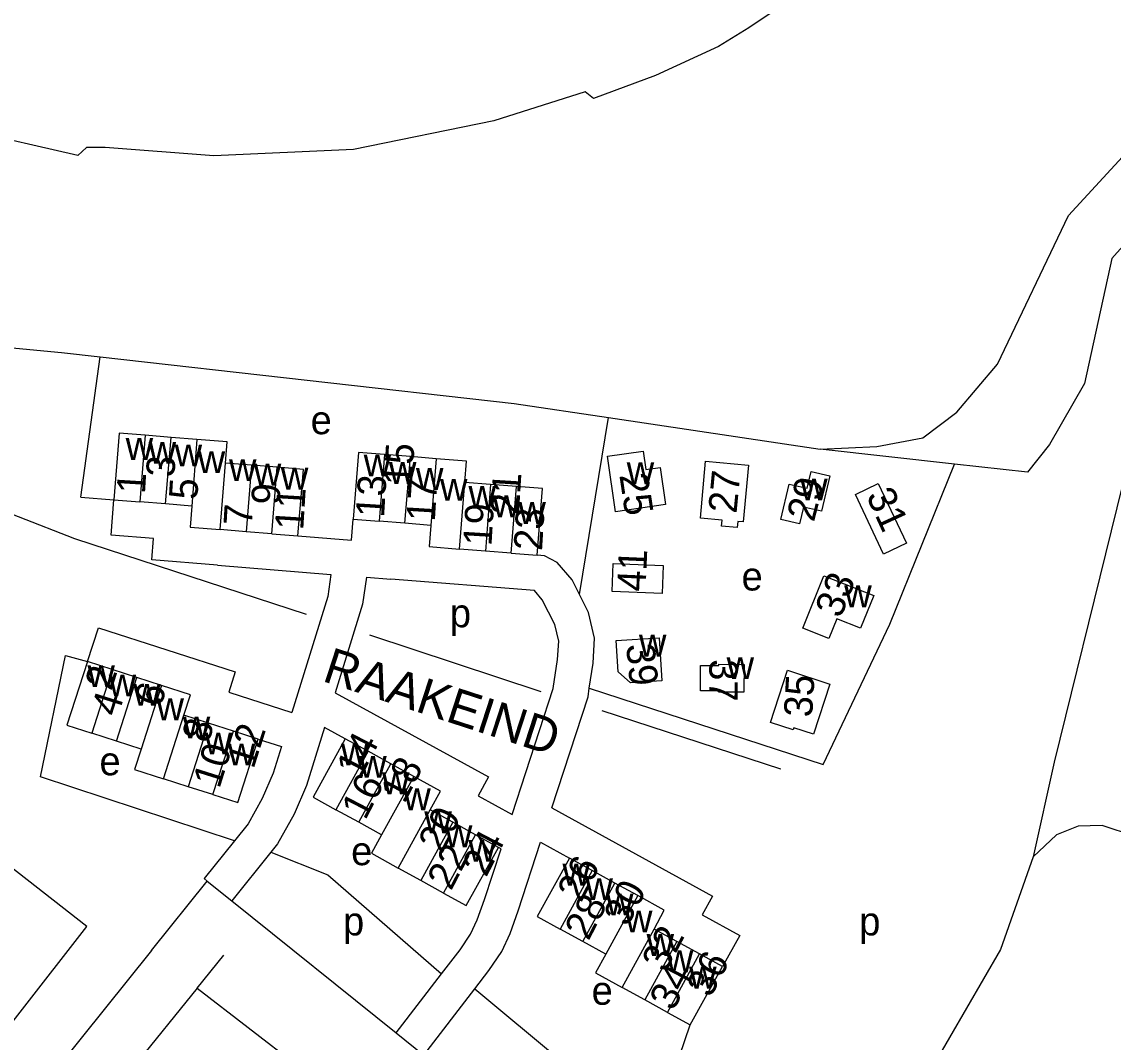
# Model space of a CAD drawing. Extents: x 159441 to 162086, y 388175 to 389787.
# Drawn here: x 160261 to 160414.4, y 389425.1 to 389568.6 of the extents above; entities that cross this region are included whole.
import ezdxf

# ---------------------------------------------------------------- set-up
doc = ezdxf.new("R2010")
doc.units = 0
for name, color, linetype in [('BLT_Basislijn', 7, 'Continuous'), ('BLT_Bebouwing', 7, 'Continuous'), ('BLT_Centroide', 7, 'Continuous'), ('BLT_Huisnummer', 7, 'Continuous'), ('BLT_Huisnummer_ tussenligend', 7, 'Continuous'), ('BLT_Huisnummer_zonder_bebouwing', 7, 'Continuous'), ('BLT_Onderverdeling_panden', 7, 'Continuous'), ('BLT_Plantopo', 7, 'Continuous'), ('BLT_Straatnaam', 7, 'Continuous')]:
    doc.layers.add(name, color=color, linetype=linetype)

msp = doc.modelspace()

# ---------------------------------------------------------------- linework, layer by layer
at = {"layer": 'BLT_Basislijn'}
for p, q in [((160269.3, 389501.74), (160272.05, 389521.43)), ((160339.43, 389488.02), (160343.47, 389512.9)), ((160343.47, 389512.9), (160373.24, 389508.47)), ((160392.13, 389506.37), (160373.24, 389508.47)), ((160269.3, 389501.74), (160273.96, 389501.36)), ((160307.34, 389495.68), (160307.58, 389498.63)), ((160299.83, 389496.3), (160307.34, 389495.68)), ((160288.51, 389492.17), (160304.46, 389490.87)), ((160309.45, 389490.46), (160312.87, 389490.18)), ((160333.1, 389488.59), (160312.87, 389490.18)), ((160334.03, 389474.34), (160309.95, 389482.3)), ((160290.1, 389474.31), (160298.98, 389471.44)), ((160406.13, 389464.49), (160403.2, 389451.16)), ((160325.19, 389459.75), (160329.97, 389457.12)), ((160296.04, 389451.83), (160290.53, 389444.96)), ((160296.49, 389452.39), (160296.44, 389452.33)), ((160403.2, 389451.16), (160398.61, 389438.15)), ((160279.23, 389437.97), (160287.07, 389447.73)), ((160287.07, 389447.73), (160290.53, 389444.96)), ((160290.53, 389444.96), (160313.65, 389426.42)), ((160279.23, 389437.97), (160250.98, 389402.79)), ((160285.65, 389432.7), (160289.39, 389437.31)), ((160398.61, 389438.15), (160365.27, 389380.6)), ((160313.65, 389426.42), (160320.03, 389434.71)), ((160285.65, 389432.7), (160273.59, 389417.82)), ((160285.65, 389432.7), (160342.42, 389389.08)), ((160317.55, 389423.29), (160324.72, 389432.61)), ((160313.65, 389426.42), (160317.55, 389423.29))]:
    msp.add_line(p, q, dxfattribs=at)
for points in [[(160371.16, 389573.06), (160363.22, 389567.72), (160358.94, 389565.1), (160350.1, 389560.99), (160341.38, 389557.76), (160340.2, 389558.69), (160327.39, 389554.65), (160307.62, 389550.59), (160288, 389549.69), (160272.71, 389550.9), (160270.1, 389550.9), (160268.89, 389549.78), (160253.35, 389553.3), (160237.78, 389558.66), (160215.01, 389566.48), (160191.12, 389571.55)], [(160481.43, 389567.42), (160465.31, 389557.49), (160453.34, 389551.39), (160443.39, 389548.82), (160437.75, 389548.31), (160428.15, 389546.06), (160420.07, 389541.8), (160414.23, 389535.28), (160410.4, 389517.69), (160405.5, 389509.12), (160402.38, 389505.22), (160392.13, 389506.37)], [(160373.24, 389508.47), (160381.22, 389508.86), (160387.7, 389510.08), (160392.44, 389513.68), (160398.18, 389520.4), (160408.17, 389541.3), (160416.84, 389550.74)], [(160435.66, 389533.02), (160422.18, 389529.49), (160406.13, 389464.49)], [(160239.42, 389524.63), (160266.58, 389522.05), (160272.05, 389521.43)], [(160272.05, 389521.43), (160330.25, 389514.87), (160343.47, 389512.9)], [(160268.48, 389495.85), (160268.48, 389495.85), (160252.56, 389502.07), (160221.63, 389512.44)], [(160340.79, 389474.86), (160373.69, 389464.13), (160383.06, 389483.87), (160392.13, 389506.37)], [(160279.52, 389495.9), (160273.55, 389496.38), (160273.96, 389501.36)], [(160301.02, 389485.25), (160268.48, 389495.85), (160268.48, 389495.85)], [(160288.51, 389492.17), (160279.29, 389492.9), (160279.52, 389495.9)], [(160339.43, 389488.02), (160338.37, 389490.1), (160336.29, 389492.56), (160334.51, 389493.49), (160333.45, 389493.57)], [(160304.46, 389490.87), (160304.03, 389487.78), (160298.98, 389471.44)], [(160309.45, 389490.46), (160308.93, 389486.69), (160305.08, 389474.23)], [(160329.97, 389457.12), (160335.73, 389474.83), (160336.34, 389478.92), (160336.5, 389481.49), (160335.96, 389483.8), (160334.18, 389487.31), (160333.1, 389488.59)], [(160340.79, 389474.86), (160341.32, 389478.39), (160341.54, 389481.91), (160340.69, 389485.53), (160339.43, 389488.02)], [(160270.24, 389478.6), (160271.78, 389483.36), (160291.02, 389477.17), (160290.1, 389474.31)], [(160290.89, 389453.4), (160263.63, 389462.39), (160267.16, 389479.46), (160270.24, 389478.6)], [(160305.08, 389474.23), (160326.64, 389462.39), (160325.19, 389459.75)], [(160335.53, 389458.05), (160340.61, 389473.67), (160340.79, 389474.86)], [(160367.72, 389463.49), (160367.72, 389463.49), (160342.61, 389471.7)], [(160306.49, 389467.75), (160303.57, 389469.36), (160301.04, 389461.18), (160299.31, 389457.15), (160296.98, 389453), (160296.04, 389451.83)], [(160294.23, 389467.72), (160297.5, 389466.66), (160296.34, 389462.91), (160294.82, 389459.37), (160292.82, 389455.81), (160290.89, 389453.4)], [(160335.53, 389458.05), (160358.11, 389445.62), (160356.67, 389443)], [(160417.42, 389454.04), (160412.9, 389455.58), (160409.52, 389455.47), (160406.48, 389454.26), (160403.2, 389451.16)], [(160290.89, 389453.4), (160286.63, 389448.09), (160287.07, 389447.73)], [(160324.72, 389432.61), (160326.69, 389435.16), (160328.48, 389437.83), (160329.67, 389440.38), (160330.81, 389443.55), (160333.95, 389453.21), (160338, 389450.98)], [(160241.32, 389404.38), (160270.16, 389441.35), (160257, 389451.61), (160228.13, 389414.61)], [(160296.04, 389451.83), (160304.01, 389448.64), (160320.03, 389434.71)], [(160320.03, 389434.71), (160322.63, 389438.09), (160324.11, 389440.29), (160325.05, 389442.29), (160326.08, 389445.17), (160328.39, 389452.28), (160328.01, 389452.49)], [(160356.67, 389443), (160361.94, 389440.11), (160359.52, 389435.73)], [(160324.72, 389432.61), (160349.65, 389411.86), (160354.98, 389427.53)]]:
    msp.add_lwpolyline(points, dxfattribs=at)
at = {"layer": 'BLT_Bebouwing'}
for p, q in [((160281.99, 389510.13), (160278.36, 389510.43)), ((160285.63, 389509.84), (160281.99, 389510.13)), ((160293.28, 389506.21), (160289.66, 389506.5)), ((160315.64, 389507.42), (160311.99, 389507.72)), ((160319.28, 389507.13), (160315.64, 389507.42)), ((160296.92, 389505.92), (160293.28, 389506.21)), ((160326.92, 389503.51), (160323.3, 389503.8)), ((160330.55, 389503.22), (160326.92, 389503.51)), ((160273.96, 389501.36), (160277.59, 389501.07)), ((160281.23, 389500.78), (160277.59, 389501.07)), ((160284.9, 389500.48), (160281.23, 389500.78)), ((160307.58, 389498.63), (160311.24, 389498.34)), ((160292.54, 389496.87), (160288.9, 389497.16)), ((160314.88, 389498.05), (160311.24, 389498.34)), ((160318.51, 389497.76), (160314.88, 389498.05)), ((160296.18, 389496.58), (160292.54, 389496.87)), ((160296.18, 389496.58), (160299.83, 389496.3)), ((160326.18, 389494.15), (160322.54, 389494.43)), ((160329.82, 389493.86), (160326.18, 389494.15)), ((160329.82, 389493.86), (160333.45, 389493.57)), ((160273.72, 389477.49), (160270.24, 389478.6)), ((160277.19, 389476.37), (160273.72, 389477.49)), ((160280.67, 389475.25), (160277.19, 389476.37)), ((160287.28, 389469.96), (160283.81, 389471.08)), ((160290.76, 389468.84), (160287.28, 389469.96)), ((160274.32, 389467.43), (160270.84, 389468.55)), ((160294.23, 389467.72), (160290.76, 389468.84)), ((160277.79, 389466.3), (160274.32, 389467.43)), ((160309.7, 389465.99), (160306.49, 389467.75)), ((160312.9, 389464.23), (160309.7, 389465.99)), ((160316.11, 389462.47), (160312.9, 389464.23)), ((160284.41, 389461.02), (160280.93, 389462.14)), ((160287.88, 389459.9), (160284.41, 389461.02)), ((160308.39, 389456.02), (160305.18, 389457.77)), ((160321.61, 389456.02), (160318.41, 389457.78)), ((160311.6, 389454.27), (160308.39, 389456.02)), ((160324.81, 389454.25), (160321.61, 389456.02)), ((160328.01, 389452.49), (160324.81, 389454.25)), ((160317.1, 389447.82), (160313.9, 389449.58)), ((160341.2, 389449.22), (160338, 389450.98)), ((160344.4, 389447.46), (160341.2, 389449.22)), ((160320.3, 389446.06), (160317.1, 389447.82)), ((160347.6, 389445.7), (160344.4, 389447.46)), ((160339.88, 389439.24), (160336.68, 389441)), ((160353.1, 389439.25), (160349.89, 389441.01)), ((160343.1, 389437.48), (160339.88, 389439.24)), ((160356.3, 389437.5), (160353.1, 389439.25)), ((160359.52, 389435.73), (160356.3, 389437.5)), ((160354.98, 389427.53), (160359.52, 389435.73)), ((160348.59, 389431.03), (160345.4, 389432.79)), ((160351.79, 389429.28), (160348.59, 389431.03)), ((160351.79, 389429.28), (160354.98, 389427.53))]:
    msp.add_line(p, q, dxfattribs=at)
for points in [[(160278.36, 389510.43), (160274.71, 389510.72), (160273.96, 389501.36)], [(160289.66, 389506.5), (160289.9, 389509.49), (160285.63, 389509.84)], [(160311.99, 389507.72), (160308.35, 389508.01), (160307.58, 389498.63)], [(160323.3, 389503.8), (160323.54, 389506.79), (160319.28, 389507.13)], [(160299.83, 389496.3), (160300.59, 389505.62), (160296.92, 389505.92)], [(160333.45, 389493.57), (160334.22, 389502.93), (160330.55, 389503.22)], [(160284.9, 389500.48), (160284.66, 389497.49), (160288.9, 389497.16)], [(160318.51, 389497.76), (160318.26, 389494.77), (160322.54, 389494.43)], [(160270.24, 389478.6), (160267.36, 389469.68), (160270.84, 389468.55)], [(160283.81, 389471.08), (160284.73, 389473.94), (160280.67, 389475.25)], [(160287.88, 389459.9), (160291.36, 389458.79), (160294.23, 389467.72)], [(160306.49, 389467.75), (160301.95, 389459.53), (160305.18, 389457.77)], [(160277.79, 389466.3), (160276.87, 389463.44), (160280.93, 389462.14)], [(160318.41, 389457.78), (160319.85, 389460.41), (160316.11, 389462.47)], [(160311.6, 389454.27), (160310.15, 389451.65), (160313.9, 389449.58)], [(160320.3, 389446.06), (160323.5, 389444.3), (160328.01, 389452.49)], [(160338, 389450.98), (160333.48, 389442.75), (160336.68, 389441)], [(160349.89, 389441.01), (160351.33, 389443.65), (160347.6, 389445.7)], [(160343.1, 389437.48), (160341.65, 389434.84), (160345.4, 389432.79)]]:
    msp.add_lwpolyline(points, dxfattribs=at)
for points in [[(160343.34, 389507.49), (160348.37, 389508.21), (160348.74, 389505.61), (160350.74, 389505.9), (160351.5, 389500.67), (160344.46, 389499.66)], [(160368.87, 389503.56), (160371.42, 389502.98), (160371.97, 389505.34), (160374.6, 389504.73), (160373.44, 389499.74), (160370.91, 389500.34), (160370.36, 389497.98), (160367.73, 389498.58)], [(160373.78, 389490.68), (160380.78, 389487.89), (160378.94, 389483.29), (160375.58, 389484.63), (160374.48, 389481.85), (160370.83, 389483.3)], [(160344.57, 389481.57), (160350.62, 389481.95), (160350.99, 389475.9), (160346.6, 389475.62), (160344.84, 389477.17)], [(160356.43, 389478.08), (160359.02, 389478.06), (160359.02, 389478.23), (160362.54, 389478.21), (160362.52, 389474.31), (160359, 389474.33), (160359, 389474.49), (160356.41, 389474.5)]]:
    msp.add_lwpolyline(points, close=True, dxfattribs=at)
at = {"layer": 'BLT_Onderverdeling_panden'}
for p, q in [((160278.36, 389510.43), (160277.59, 389501.07)), ((160281.23, 389500.78), (160281.99, 389510.13)), ((160285.63, 389509.84), (160284.9, 389500.48)), ((160288.9, 389497.16), (160289.66, 389506.5)), ((160311.99, 389507.72), (160311.24, 389498.34)), ((160314.88, 389498.05), (160315.64, 389507.42)), ((160319.28, 389507.13), (160318.51, 389497.76)), ((160293.28, 389506.21), (160292.54, 389496.87)), ((160296.18, 389496.58), (160296.92, 389505.92)), ((160322.54, 389494.43), (160323.3, 389503.8)), ((160326.92, 389503.51), (160326.18, 389494.15)), ((160329.82, 389493.86), (160330.55, 389503.22)), ((160273.72, 389477.49), (160270.84, 389468.55)), ((160274.32, 389467.43), (160277.19, 389476.37)), ((160280.67, 389475.25), (160277.79, 389466.3)), ((160280.93, 389462.14), (160283.81, 389471.08)), ((160287.28, 389469.96), (160284.41, 389461.02)), ((160287.88, 389459.9), (160290.76, 389468.84)), ((160309.7, 389465.99), (160305.18, 389457.77)), ((160308.39, 389456.02), (160312.9, 389464.23)), ((160316.11, 389462.47), (160311.6, 389454.27)), ((160313.9, 389449.58), (160318.41, 389457.78)), ((160321.61, 389456.02), (160317.1, 389447.82)), ((160320.3, 389446.06), (160324.81, 389454.25)), ((160341.2, 389449.22), (160336.68, 389441)), ((160339.88, 389439.24), (160344.4, 389447.46)), ((160347.6, 389445.7), (160343.1, 389437.48)), ((160345.4, 389432.79), (160349.89, 389441.01)), ((160353.1, 389439.25), (160348.59, 389431.03)), ((160351.79, 389429.28), (160356.3, 389437.5))]:
    msp.add_line(p, q, dxfattribs=at)
at = {"layer": 'BLT_Plantopo'}
for points in [[(160357.11, 389506.77), (160363.15, 389506.21), (160362.41, 389498.24), (160361.65, 389498.31), (160361.57, 389497.46), (160359.38, 389497.65), (160359.45, 389498.5), (160356.42, 389498.77)], [(160378.22, 389502.12), (160381.41, 389503.65), (160385.4, 389495.27), (160382.16, 389493.69)], [(160344.14, 389492.38), (160351.16, 389492.13), (160351.02, 389488.2), (160344, 389488.45)], [(160368.66, 389477.4), (160374.62, 389475.45), (160372.31, 389468.39), (160369.55, 389469.3), (160369.46, 389469.01), (160366.25, 389470.06)]]:
    msp.add_lwpolyline(points, close=True, dxfattribs=at)

# ---------------------------------------------------------------- texts
at = {"layer": 'BLT_Centroide'}
for s, p in [('e', (160301.62, 389510.57)), ('w', (160275.61, 389506.97)), ('w', (160278.84, 389506.41)), ('w', (160282.5, 389506.05)), ('w', (160285.74, 389505.1)), ('w', (160290.14, 389503.98)), ('w', (160293.62, 389503.34)), ('w', (160309.07, 389504.64)), ('w', (160312.62, 389503.58)), ('w', (160346.05, 389503.54)), ('w', (160297.43, 389502.78)), ('w', (160316.42, 389502.74)), ('w', (160319.8, 389501.22)), ('w', (160323.81, 389500.2)), ('w', (160370.44, 389501.27)), ('w', (160327.19, 389498.9)), ('w', (160330.82, 389497.95)), ('e', (160362.2, 389488.6)), ('w', (160376.63, 389486.24)), ('p', (160321.19, 389483.43)), ('w', (160347.77, 389479.31)), ('w', (160360.09, 389476.14)), ('w', (160270.23, 389475.03)), ('w', (160273.22, 389473.72)), ('w', (160276.67, 389472.39)), ('w', (160279.94, 389470.35)), ('w', (160283.64, 389467.81)), ('w', (160286.7, 389465.56)), ('w', (160289.97, 389464.01)), ('w', (160305.88, 389464.01)), ('e', (160271.93, 389462.62)), ('w', (160308.45, 389462.28)), ('w', (160311.65, 389459.96)), ('w', (160314.64, 389457.71)), ('w', (160317.6, 389454.47)), ('w', (160320.49, 389452.5)), ('e', (160307.31, 389449.98)), ('w', (160323.79, 389450.46)), ('w', (160337.02, 389447.11)), ('w', (160340.25, 389445.07)), ('w', (160343.14, 389442.92)), ('w', (160345.81, 389440.53)), ('p', (160306.17, 389440.11)), ('p', (160378.74, 389440.11)), ('w', (160348.84, 389437.22)), ('w', (160351.55, 389434.93)), ('w', (160354.82, 389432.64)), ('e', (160341.12, 389430.36))]:
    msp.add_text(s, height=4, dxfattribs=at).set_placement(p)
at = {"layer": 'BLT_Huisnummer'}
for s, rotation, p in [('1', 86.5267, (160278.32, 389502.12)), ('25', 278.5267, (160345.01, 389504.83)), ('5', 86.5267, (160285.67, 389501.3)), ('13', 86.5267, (160311.93, 389498.8)), ('17', 86.5267, (160319.07, 389498.22)), ('29', 75.5267, (160372.36, 389498.12)), ('11', 86.5267, (160300.57, 389497.03)), ('7', 86.5267, (160293.35, 389497.65)), ('19', 86.5267, (160327.03, 389494.79)), ('23', 86.5267, (160334.14, 389494.13)), ('33', 68.5267, (160376.12, 389484.57)), ('39', 275.5267, (160345.96, 389480.97)), ('37', 269.5267, (160357.68, 389478.95)), ('2', 72.5267, (160273.59, 389474.39)), ('6', 72.5267, (160280.52, 389472.02)), ('8', 72.5267, (160287.23, 389466.99)), ('12', 72.5267, (160293.58, 389463.4)), ('14', 62.5267, (160308.57, 389461.97)), ('18', 62.5267, (160314.77, 389458.52)), ('20', 62.5267, (160320.09, 389451.49)), ('24', 62.5267, (160326.28, 389448.18)), ('26', 62.5267, (160339.63, 389444.61)), ('30', 62.5267, (160346.16, 389441.21)), ('32', 62.5267, (160351.52, 389434.78)), ('36', 62.5267, (160357.83, 389431.22))]:
    msp.add_text(s, height=4, rotation=rotation, dxfattribs=at).set_placement(p)
at = {"layer": 'BLT_Huisnummer_ tussenligend'}
for s, rotation, p in [('15', 86.5267, (160315.86, 389503.27)), ('3', 86.5267, (160282.45, 389504.46)), ('21', 86.5267, (160330.89, 389499.15)), ('9', 86.5267, (160297.24, 389500.57)), ('4', 72.5267, (160274.5, 389470.72)), ('10', 72.5267, (160288.78, 389460.64)), ('16', 62.5267, (160309.29, 389456.2)), ('22', 62.5267, (160321.35, 389446.28)), ('28', 62.5267, (160340.67, 389439.24)), ('34', 62.5267, (160352.6, 389429.36))]:
    msp.add_text(s, height=4, rotation=rotation, dxfattribs=at).set_placement(p)
at = {"layer": 'BLT_Huisnummer_zonder_bebouwing'}
for s, rotation, p in [('27', 84.5267, (160361.48, 389499.35)), ('31', 294.5267, (160379.66, 389501.95)), ('41', 87.5267, (160348.69, 389488.39)), ('35', 86.5267, (160372.11, 389470.71))]:
    msp.add_text(s, height=4, rotation=rotation, dxfattribs=at).set_placement(p)
at = {"layer": 'BLT_Straatnaam'}
msp.add_text('RAAKEIND', height=5, rotation=342.0004, dxfattribs=at).set_placement((160303.1, 389475.91))

doc.saveas('drawing.dxf')
